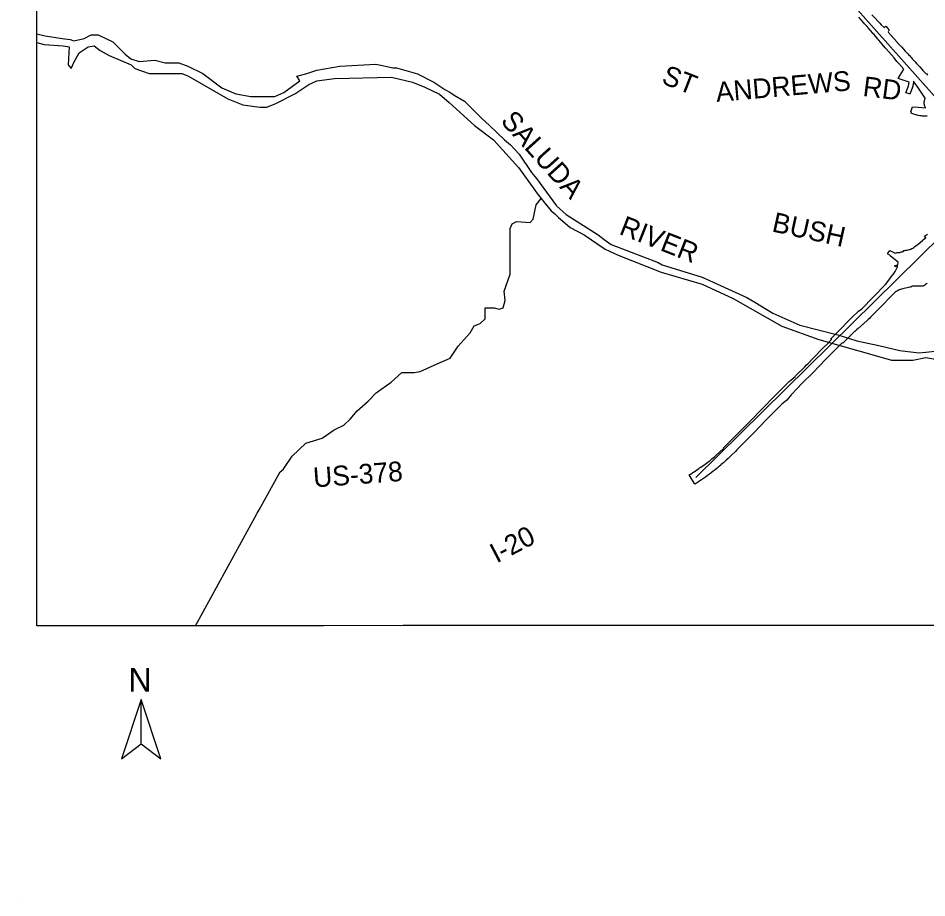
# Model space of a CAD drawing. Extents: x 1936118 to 1997618, y 780614 to 828614.
# Drawn here: x 1936118 to 1963667, y 780614 to 807292 of the extents above; entities that cross this region are included whole.
import ezdxf

# ---------------------------------------------------------------- set-up
doc = ezdxf.new("R2010")
doc.units = 0
for name, color, linetype in [('North Arrow', 7, 'Continuous'), ('RD_EX_H2O_BlueLn', 7, 'Continuous'), ('RD_SHT_ID', 7, 'Continuous'), ('RD_SHT_Misc3', 7, 'Continuous'), ('RD_SHT_Misc4', 7, 'Continuous'), ('RD_SHT_ShtClip', 7, 'Continuous')]:
    doc.layers.add(name, color=color, linetype=linetype)

msp = doc.modelspace()

# ---------------------------------------------------------------- linework, layer by layer
at = {"layer": 'North Arrow'}
for p, q in [((1939847, 786634), (1939247, 784834)), ((1939847, 786634), (1939247, 784834)), ((1940447, 784834), (1939847, 786634)), ((1939847, 785284), (1939847, 786634)), ((1939847, 785284), (1939847, 786634)), ((1939247, 784834), (1939847, 785284)), ((1939247, 784834), (1939847, 785284)), ((1939847, 785284), (1940447, 784834))]:
    msp.add_line(p, q, dxfattribs=at)
at = {"layer": 'RD_EX_H2O_BlueLn'}
for points in [[(1963673, 804320), (1963643, 804320), (1963643, 804320), (1963618, 804320), (1963563, 804322), (1963537, 804324), (1963509, 804327), (1963458, 804334), (1963454, 804334), (1963401, 804344), (1963379, 804349), (1963347, 804356), (1963294, 804370), (1963242, 804387), (1963191, 804406), (1963204, 804441), (1963204, 804442), (1963179, 804452), (1963230, 804604), (1963401, 804592), (1963624, 804575), (1963613, 804599), (1963604, 804623), (1963597, 804648), (1963592, 804673), (1963589, 804698), (1963588, 804724), (1963589, 804738), (1963590, 804750), (1963592, 804765), (1963593, 804775), (1963599, 804801), (1963607, 804825), (1963615, 804850), (1963619, 804865), (1963394, 805197), (1963391, 805201), (1963287, 805354), (1963268, 805382), (1963261, 805363), (1963259, 805330), (1963259, 805329), (1963255, 805296), (1963250, 805263), (1963248, 805256), (1963243, 805230), (1963234, 805197), (1963223, 805165), (1963156, 804983), (1963127, 804994), (1963070, 805014), (1963034, 805028), (1963101, 805210), (1963112, 805244), (1963120, 805278), (1963126, 805313), (1963130, 805348), (1962797, 805460), (1962974, 805742), (1962819, 805913), (1962789, 805947), (1962759, 805982), (1962760, 805982), (1962673, 806084), (1962521, 806262), (1962408, 806394), (1962315, 806503), (1962215, 806620), (1962176, 806666), (1962137, 806712), (1962122, 806729), (1962067, 806793), (1962035, 806831), (1962031, 806835), (1961892, 806994), (1961888, 806999), (1961876, 807013), (1961866, 807024), (1961853, 807039), (1961839, 807055), (1961827, 807067), (1961812, 807085), (1961797, 807102), (1961777, 807124), (1961748, 807157), (1961603, 807318)], [(1962000, 807397), (1962101, 807289), (1962185, 807200), (1962245, 807136), (1962286, 807092), (1962370, 807004), (1962375, 806998), (1962375, 806998), (1962426, 807044), (1962500, 806964), (1962524, 806938), (1962497, 806877), (1962503, 806857), (1962667, 806676), (1962773, 806559), (1962773, 806558), (1962812, 806516), (1962830, 806496), (1962905, 806413), (1963012, 806295), (1963089, 806209), (1963136, 806157), (1963138, 806156), (1963190, 806098), (1963193, 806095), (1963234, 806049), (1963241, 806041), (1963272, 806008), (1963289, 805989), (1963310, 805967), (1963354, 805920), (1963401, 805870), (1963455, 805812), (1963511, 805751), (1963551, 805708), (1963579, 805677), (1963646, 805603), (1963654, 805609), (1963689, 805568)], [(1936683, 806821), (1936932, 806757), (1937454, 806671), (1937697, 806640), (1937811, 806602), (1938117, 806673), (1938332, 806785), (1938543, 806785), (1938993, 806569), (1939362, 806201), (1939539, 806055), (1939782, 805981), (1940266, 806017), (1940571, 805939), (1940990, 805940), (1941264, 805838), (1941720, 805612), (1942292, 805179), (1942718, 804997), (1943170, 804919), (1943900, 804918), (1944176, 805033), (1944655, 805389), (1944565, 805535)], [(1936683, 806553), (1936907, 806497), (1937480, 806456), (1937665, 806427), (1937630, 805876), (1937727, 805768), (1937809, 805947), (1937964, 806242), (1938237, 806424), (1938420, 806457), (1938604, 806310), (1938878, 806164), (1939540, 805873), (1939660, 805766), (1940087, 805613), (1941084, 805612), (1941263, 805541), (1942477, 804850), (1942929, 804668), (1943443, 804597), (1943654, 804597), (1943928, 804702), (1944507, 804994), (1944926, 805284), (1945170, 805391), (1945714, 805464), (1947440, 805500), (1948076, 805354), (1948446, 805201), (1948896, 804985), (1949187, 804736)], [(1944565, 805535), (1944837, 805604), (1945170, 805717), (1945871, 805831), (1946962, 805898), (1947167, 805859), (1947473, 805785), (1947593, 805782)], [(1947593, 805782), (1948229, 805600), (1948718, 805352), (1949050, 805129), (1949201, 805052)], [(1949201, 805052), (1949341, 804955)], [(1949187, 804736), (1949951, 804035), (1950529, 803599), (1951284, 802759), (1951780, 802076)], [(1949341, 804955), (1949654, 804771), (1949771, 804654)], [(1949771, 804654), (1950167, 804256), (1950409, 804036), (1950861, 803600), (1951044, 803452), (1951312, 803163), (1951678, 802611), (1951829, 802429), (1952435, 801600), (1952734, 801342), (1953705, 800722), (1953882, 800576), (1954093, 800430), (1955519, 799877)], [(1951780, 802076), (1951853, 801978)], [(1951853, 801978), (1951970, 801822)], [(1950125, 798030), (1950272, 798175), (1950272, 798504), (1950546, 798504), (1950698, 798470), (1950821, 798504), (1950883, 798725), (1950853, 799013), (1951036, 799525), (1951038, 800909), (1951099, 801055), (1951224, 801123), (1951643, 801091), (1951733, 801192), (1951828, 801632), (1951970, 801822)], [(1951970, 801822), (1952090, 801678), (1952280, 801449), (1952324, 801410)], [(1952324, 801410), (1952385, 801356), (1952504, 801251), (1952632, 801139)], [(1952632, 801139), (1952854, 800944), (1953280, 800722), (1953916, 800287), (1954308, 800103), (1955613, 799589), (1956853, 799226), (1957793, 798789), (1959276, 797947), (1960390, 797548), (1962214, 797036), (1962601, 796925), (1963240, 796924), (1963634, 797000)], [(1963676, 799256), (1963653, 799234), (1963629, 799214), (1963604, 799195), (1963577, 799178), (1963550, 799163), (1963363, 799165), (1963359, 799165), (1963277, 799162), (1963236, 799161), (1963208, 799149), (1963179, 799138), (1963150, 799129), (1962937, 799079), (1962902, 799071), (1962867, 799061), (1962833, 799049), (1962800, 799034), (1962768, 799017), (1962737, 798999), (1962708, 798978), (1962570, 798838), (1962313, 798576), (1962104, 798364), (1962103, 798363), (1962021, 798280), (1961963, 798221), (1961927, 798185), (1961889, 798149), (1961858, 798121), (1961851, 798115), (1961588, 797884), (1961538, 797838), (1961489, 797790), (1961481, 797797), (1961360, 797675), (1961344, 797658), (1961125, 797435), (1961098, 797445), (1961086, 797432), (1960926, 797270), (1960923, 797266), (1960610, 796948), (1960209, 796540), (1959902, 796229), (1959551, 795871), (1959428, 795711), (1959270, 795586), (1959016, 795328), (1959011, 795323), (1958798, 795106), (1958429, 794730), (1958221, 794518), (1957905, 794197), (1957862, 794154), (1957748, 794037), (1957694, 793986), (1957641, 793936), (1957586, 793885), (1957532, 793836), (1957500, 793808), (1957476, 793787), (1957437, 793753), (1957420, 793739), (1957370, 793697), (1957364, 793691), (1957307, 793644), (1957249, 793598), (1957192, 793552), (1957133, 793507), (1957122, 793498), (1957074, 793462), (1957015, 793418), (1956955, 793375), (1956895, 793332), (1956834, 793291), (1956787, 793259), (1956773, 793249), (1956711, 793209), (1956649, 793169), (1956631, 793157), (1956459, 793439), (1956505, 793467), (1956549, 793495), (1956558, 793501), (1956573, 793511), (1956598, 793527), (1956642, 793558), (1956657, 793568), (1956687, 793589), (1956752, 793636), (1956787, 793660), (1956793, 793664), (1956799, 793668), (1956815, 793678), (1956859, 793707), (1956902, 793736), (1956944, 793766), (1956986, 793796), (1957028, 793827), (1957069, 793859), (1957094, 793878), (1957109, 793891), (1957119, 793898), (1957149, 793924), (1957189, 793957), (1957228, 793991), (1957251, 794012), (1957266, 794026), (1957500, 794240), (1957503, 794242), (1957497, 794247), (1958310, 795073), (1959040, 795816), (1959081, 795857), (1959112, 795888), (1959161, 795939), (1959492, 796275), (1959540, 796315), (1959675, 796428), (1959689, 796440), (1959781, 796533), (1959877, 796631), (1959967, 796722), (1960023, 796779), (1960056, 796813), (1960220, 796979), (1960526, 797290), (1960644, 797410), (1960739, 797507), (1960785, 797554), (1960759, 797563), (1960761, 797565), (1960949, 797756), (1960969, 797777), (1961385, 798199), (1961591, 798408), (1961694, 798478), (1961695, 798478), (1962039, 798829), (1962419, 799215), (1962574, 799426), (1962580, 799434), (1962644, 799520), (1962705, 799604), (1962792, 799769), (1962782, 799775), (1962704, 799755), (1962697, 799782), (1962695, 799789), (1962786, 799812), (1962802, 799891), (1962569, 800069), (1962568, 800069), (1962563, 800073), (1962571, 800085), (1962541, 800104), (1962478, 800144), (1962541, 800249), (1962570, 800231), (1962571, 800231), (1962706, 800164), (1962773, 800187), (1962810, 800187), (1962852, 800188), (1962873, 800197), (1962893, 800204), (1962915, 800209), (1962937, 800211), (1962959, 800212), (1962960, 800247), (1962996, 800248), (1963004, 800248), (1963033, 800251), (1963070, 800256), (1963106, 800265), (1963141, 800275), (1963175, 800288), (1963182, 800291), (1963209, 800304), (1963241, 800321), (1963272, 800341), (1963302, 800363), (1963338, 800392), (1963401, 800442), (1963540, 800553), (1963571, 800577), (1963571, 800577), (1963637, 800630), (1963600, 800676), (1963684, 800742)], [(1955519, 799877), (1955639, 799809), (1956854, 799440), (1958213, 798819), (1958457, 798675), (1959003, 798346), (1959818, 797984), (1960968, 797692), (1961541, 797510), (1962213, 797362), (1962846, 797216), (1963422, 797139), (1963637, 797163)], [(1948819, 796806), (1949212, 796976), (1949456, 797344), (1949819, 797748), (1949940, 797960), (1950125, 798030)], [(1963634, 797000), (1964695, 796817), (1965572, 796739), (1966759, 796771), (1968119, 796555), (1968450, 796552), (1968660, 796592), (1969023, 796770), (1969298, 796812), (1969417, 796738), (1969543, 796629), (1969569, 796523), (1969569, 796193), (1969543, 796009), (1969506, 795468), (1969541, 795314), (1969720, 795138), (1970053, 794733), (1970232, 794557), (1970383, 794375)], [(1963637, 797163), (1964087, 797216), (1965358, 797030), (1965812, 796999)], [(1944060, 793537), (1944155, 793605), (1944423, 794005), (1944843, 794407), (1945335, 794551), (1945697, 794804), (1945997, 794948), (1946181, 795130), (1946399, 795383), (1946730, 795673), (1946972, 795926), (1947426, 796253), (1947755, 796548), (1948123, 796550), (1948302, 796581), (1948819, 796806)], [(1948819, 796806), (1948819, 796806)], [(1943425, 792378), (1944060, 793537)], [(1943369, 792278), (1943425, 792378)], [(1941496, 788861), (1943359, 792259)], [(1943359, 792259), (1943369, 792278)]]:
    msp.add_lwpolyline(points, dxfattribs=at)
at = {"layer": 'RD_SHT_ID'}
msp.add_line((1936118, 780614), (1936118, 780614), dxfattribs=at)
at = {"layer": 'RD_SHT_Misc4'}
for p, q in [((1959396, 810005), (1966734, 801722)), ((1956667, 793363), (1964119, 800706))]:
    msp.add_line(p, q, dxfattribs=at)
at = {"layer": 'RD_SHT_ShtClip'}
msp.add_lwpolyline([(1936683, 827674), (1979343, 827674), (1979343, 811384), (1997169, 811384), (1997169, 788874), (1947786, 788874), (1945387, 788861), (1936683, 788861)], close=True, dxfattribs=at)

# ---------------------------------------------------------------- texts
at = {"layer": 'North Arrow'}
msp.add_text('N', height=720, rotation=360, dxfattribs=at).set_placement((1939465, 786868))
at = {"layer": 'RD_SHT_Misc3'}
for s, rotation, p in [('ST', 338.7198, (1955592, 805326)), ('ANDREWS', 4.9438, (1957296, 804750)), ('RD', 352.8541, (1961706, 804936)), ('SALUDA', 311.9853, (1950721, 804152)), ('RIVER', 338.389, (1954308, 800755)), ('BUSH', 347.6235, (1958944, 800828)), ('US-378', 4.2207, (1945084, 793060)), ('I-20', 27.5976, (1950624, 790753))]:
    msp.add_text(s, height=600, rotation=rotation, dxfattribs=at).set_placement(p)

doc.saveas('drawing.dxf')
